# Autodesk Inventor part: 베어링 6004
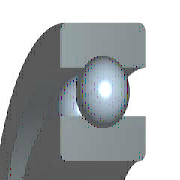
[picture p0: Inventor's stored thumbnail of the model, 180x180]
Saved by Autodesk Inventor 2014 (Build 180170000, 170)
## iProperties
Created: 2012-02
Part Number: 베어링 6004
Material: 강철, 연강
Description: 깊은 그루브 볼 베어링
Document SubType Name: Modeling
Standard: KS B 2023
Designer: mduedu
Standards Organization: KS
Language: ko-KR
Size Designation: 6004 - 20 x 42 x 12
Categories: <MemberInstance><Categories><Category DisplayName="샤프트 부품" InternalName="7f7aeb1f-a693-4053-b835-cee3144e0d98" Mnemonic="SHFT"><Category DisplayName="베어링" Inter
Density: 1 g/cm^3
Appearance: Yellow
IsCustomPart: 1
Author: mduedu
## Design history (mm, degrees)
sketch "스케치" dims "d0" = 5.72 (= -0.26 x WD + 0.26 x BD)
  geometry: L1 (3.14, 15.5)-(8.86, 15.5); L2 (6, 15.5)-(6, 12.64); L3 (6, 15.5)-(6, 18.36); L4 (3.875, 13.586)-(0, 13.586); L5 (0, 10)-(12, 10); L6 (3.875, 17.414)-(0, 17.414); L7 (0, 21)-(12, 21); L8 (12, 10)-(12, 13.586); L9 (8.125, 13.586)-(12, 13.586); L10 (8.125, 17.414)-(12, 17.414); L11 (12, 21)-(12, 17.414); L12 (-1.4, 0)-(8.4, 0) reference; L13 (0, -0.3)-(0, 5.3) reference
  constraints: 22 end point, 4 point on line, 2 collinear, 2 perpendicular, 2 symmetric about line, 1 midpoint, 1 parallel, 14 other
  dimensions: "d9" = 20 diameter of L5 L12 (= WD); "d11" = 42 diameter of L7 L12 (= BD); "d12" = 12 distance between parallel lines of L8 L13 (= KB); "d13" = 27.172 diameter of L9 L12 (= 0.326 x BD + 0.674 x WD)
revolve "본체" stored, may be unused: angle "d6" = 90 deg
revolve "볼" stored, may be unused: angle "d7" = 90 deg
pattern_circular "IDS_ARRAYBALL[SIMPL:T]" dims angle "d3" = 360 deg
body "Solid1"
fillet "모깎기1" dims "d1" = 0.6 (= KRS)
other parameters: "WD" = 20 [user parameter; used in 5 equation terms], "BD" = 42 [user parameter; used in 5 equation terms], "KB" = 12 [user parameter; used in 1 equation term], "KRS" = 0.6 [user parameter; used in 1 equation term], "d4" = 0, "d5" = 0, "d8" = 0, "d14" = 0, "d15" = 0, "BBA" = 0 [user parameter], "BC0" = 5000000 [user parameter], "BC" = 9360000 [user parameter], "BR" = 21 (= 0.5 x BD) [user parameter]
